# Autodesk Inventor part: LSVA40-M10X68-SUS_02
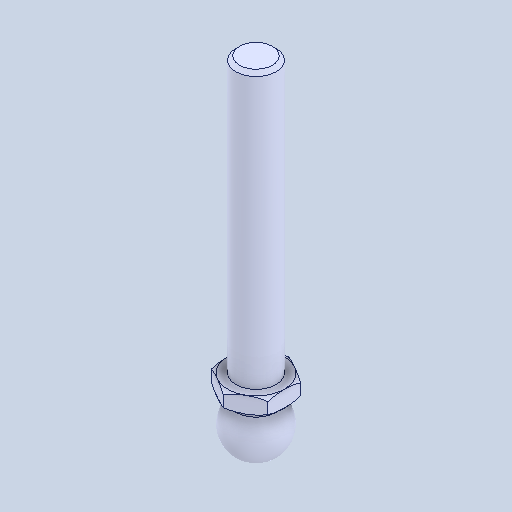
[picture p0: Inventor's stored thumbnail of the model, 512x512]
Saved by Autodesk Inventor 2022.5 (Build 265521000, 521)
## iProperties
Created: 2024-08
Part Number: LSVA40-M10X68-SUS_02
Material: 一般
Document SubType Name: Modeling
Designer: ImaoCorp
Density: 1 g/cm^3
Appearance: 既定
Author: ImaoCorp
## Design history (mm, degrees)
feature "LSVA40-M10X68-SUS_02"
node "ソリッド1"
